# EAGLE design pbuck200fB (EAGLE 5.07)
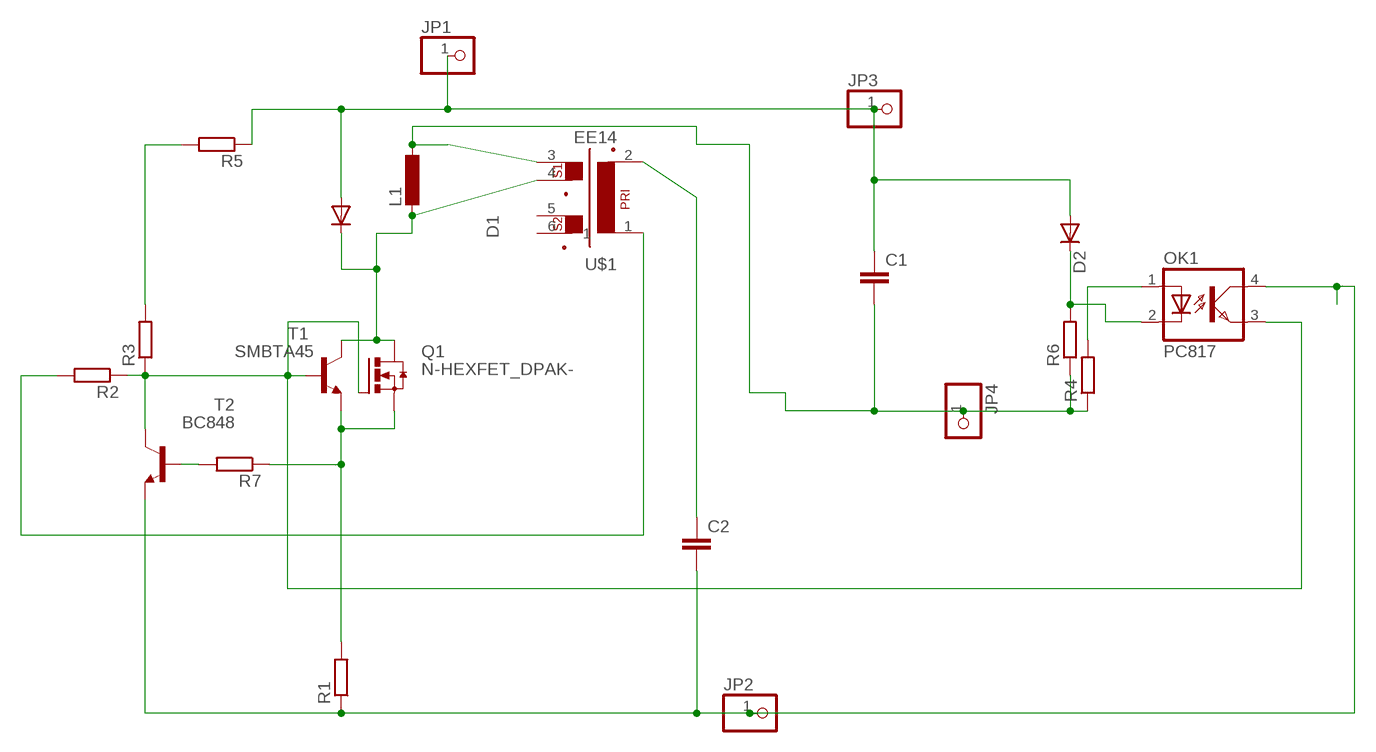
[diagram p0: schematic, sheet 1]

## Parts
C1  C-EU025-025X050  [C025-025X050]
C2  C-EUC0805  [C0805]
D1  DIODE-SMC  [SMC]
D2  DIODE-MINIMELF  [MINIMELF]
JP1  PINHD-1X11MM6  [1X1MM8]
JP2  PINHD-1X11MM6  [1X1MM8]
JP3  PINHD-1X11MM6  [1X1MM8]
JP4  PINHD-1X11MM6  [1X1MM8]
L1  L-EU0204/5  [0204/5]
OK1  PC817  [DIL04]
Q1  N-HEXFET_DPAK-  [TO252]
R1  R-EU_R1206  [R1206]
R2  R-EU_R0805  [R0805]
R3  R-EU_R1206  [R1206]
R4  R-EU_R0805  [R0805]
R5  R-EU_R1206  [R1206]
R6  R-EU_R0805  [R0805]
R7  R-EU_R1206  [R1206]
T1  SMBTA45  BC848  [SOT23]
T2  BC848  [SOT23]
U$1  EE14  [EE14]

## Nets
-: C1.1 D1.A D2.A JP1.1 JP3.1 R5.1
B1C2: OK1.3(EMIT) Q1.1(G) R2.1 R3.1 T1.B T2.C
C1: D1.C L1.2 Q1.3(D) T1.C U$1.4
EB: Q1.2(S) R1.2 R7.1 T1.E
N$1: R3.2 R5.2
N$3: R7.2 T2.B
N$4: R2.2 U$1.1
N$6: C2.1 U$1.2
N$7: D2.C OK1.2(C) R6.2
N$8: OK1.1(A) R4.2
OUT+: C1.2 JP4.1 L1.1 R4.1 R6.1 U$1.3
VPLUS: C2.2 JP2.1 OK1.4(COL) R1.1 T2.E
Unconnected: U$1.5 U$1.6

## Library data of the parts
C1 C2 = rcl:C-EU: CAPACITOR, European symbol
D1 D2 = diode:DIODE-: DIODE
JP1-JP4 = pinhead:PINHD-1X1: PIN HEADER
L1 = rcl:L-EU: INDUCTOR, European symbol
OK1 = optocoupler:PC817: SHARP OPTO COUPLER
Q1 = transistor-power:N-HEXFET_?-*: HEXFET® Power MOSFET
R1-R7 = rcl:R-EU_: RESISTOR, European symbol
T1 T2 = transistor:BC848: NPN TRANSISTOR
U$1 = trafo:EE14

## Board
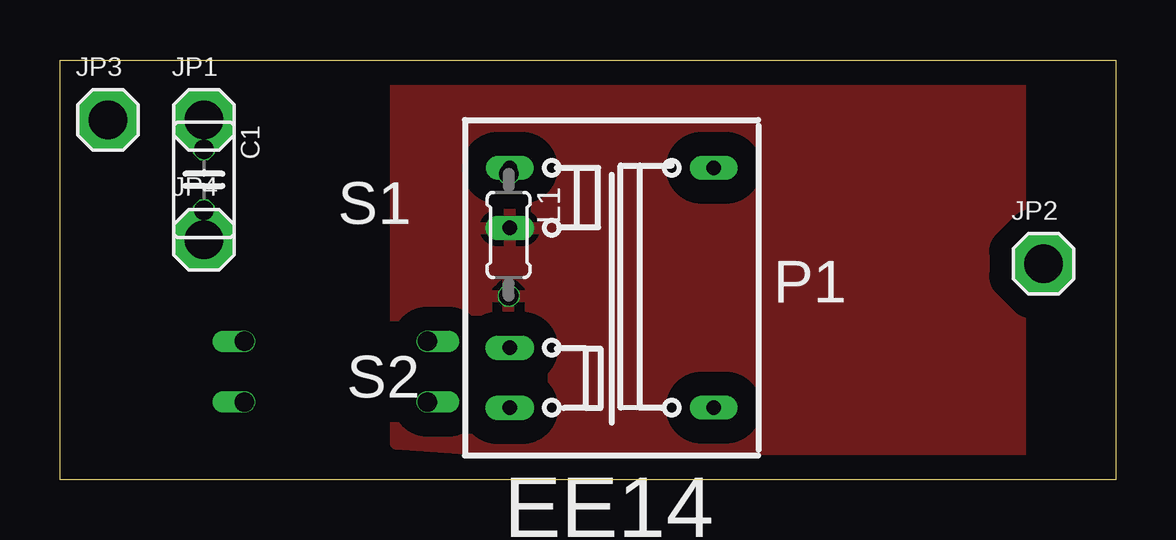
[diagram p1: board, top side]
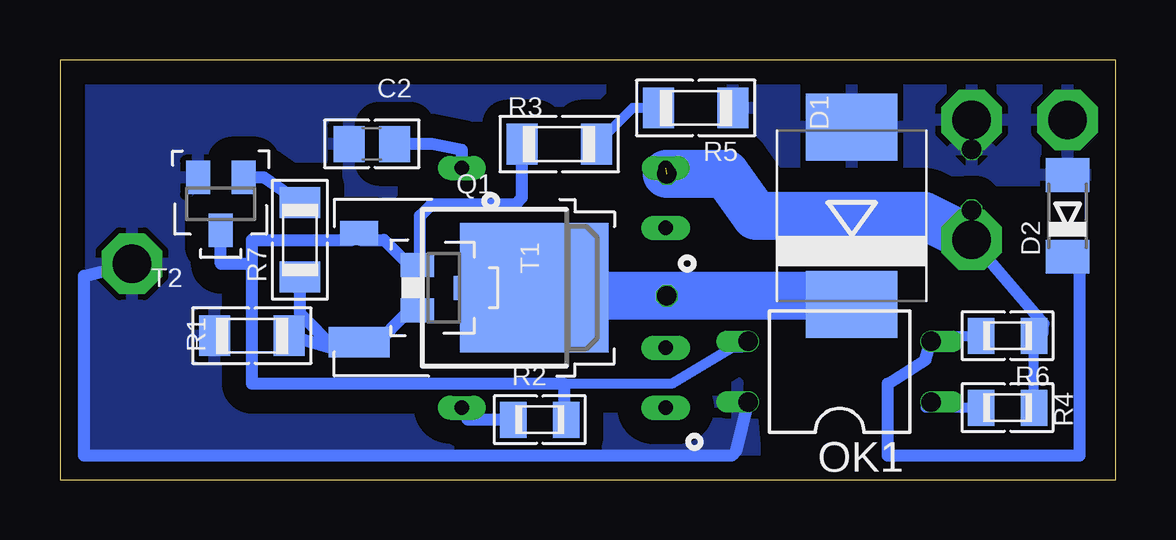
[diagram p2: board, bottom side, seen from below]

Size 44 x 17.5 mm. Coordinates in mm from the lower left corner, seen from the top.
Outline: 0,17.5 44,17.5 44,0 0,0 0,17.5
Copper layers (1*16): Top 0.035mm / dielectric 1.5mm / Bottom 0.035mm
Design rules "default": minimum track width 10mil, minimum drill 20mil, track to track 8mil, track to pad 8mil, pad to pad 8mil, via to via 8mil, smd to smd 8mil, copper to edge 40mil, drill to drill 8mil, minimum pad ring 1mil, minimum via ring 8mil, stop-mask expansion 4mil, vias tented up to drill 0mil, thermal gap 10mil

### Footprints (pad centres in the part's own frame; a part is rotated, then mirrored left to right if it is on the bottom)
C025-025X050 = drill 0.813 octagon: 1 -1.27,0; 2 1.27,0
C0805 = smd 1.3 x 1.5: 1 -0.95,0; 2 0.95,0
SMC = smd 2.8 x 3.8: A 3.7,0; C -3.7,0
MINIMELF = smd 1.4 x 1.8: A 1.7,0; C -1.7,0
1X1MM8 = drill 1.6 pad 2.54 octagon: 1 0,0
0204/5 = drill 0.813 octagon: 1 -2.54,0; 2 2.54,0
DIL04 = drill 0.813 offset: 1 -1.27,-3.81; 2 1.27,-3.81; 3 1.27,3.81; 4 -1.27,3.81
TO252 = smd 1 x 1.6: 1 -2.28,-3.53 | smd 1.27 x 2.54: 2 2.28,-3.53 | smd 5.4 x 6.2: 3 0,3.77
R1206 = smd 1.3 x 1.7: 1 -1.55,0; 2 1.55,0
R0805 = smd 1.1 x 1.5: 1 -1.1,0; 2 1.1,0
SOT23 = smd 1 x 1.4: B -0.95,-1.1; C 0,1.1; E 0.95,-1.1
EE14 = drill 0.6 pad 1 long: 1 4.25,-5; 2 4.25,5; 3 -4.25,5 | drill 0.6 pad 1.016 long: 4 -4.25,2.5; 5 -4.25,-2.5; 6 -4.25,-5

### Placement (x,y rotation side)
C1  6,12.5 270 top
C2  31,14 180 bottom
D1  11,11 90 bottom
D2  2,11 90 bottom
JP1  6,15 0 top
JP2  41,9 0 top
JP3  2,15 0 top
JP4  6,10 0 top
L1  18.7,10.2 270 top
OK1  11.5,4.5 90 bottom
Q1  28,8 270 bottom
R1  36,6 0 bottom
R2  24,2.5 180 bottom
R3  23.19,13.99 0 bottom
R4  4.5,3 180 bottom
R5  17.5,15.5 180 bottom
R6  4.5,6 180 bottom
R7  34,10 90 bottom
T1  28,8 270 bottom
T2  37.3,11.5 180 bottom
U$1  23,8 0 top

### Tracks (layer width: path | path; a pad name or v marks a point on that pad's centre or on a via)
-
  pour Bottom (isolate 1, rank 2): 1.5,16.5 16,16.5 16,13.5 15,12.5 1,12.5
B1C2
  Bottom 0.406: 23,4 18.5,4 16,5.5 15.58,5.5 OK1.3 | 31.8,10 31.2,10 31.17,10.03
  Bottom 0.5: R3.1 24.74,11.76 25,11.5 28.5,11.5 29,11 29,9.05 T1.B 29.45,8.95 30.5,10 31.5,10 Q1.1 31.17,10.03 | T2.C 37.3,9 36,9 | 36,9 36,10 31.8,10 | R2.1 23,2.6 23,4 36,4 36,9
C1
  Bottom 0.406: 24.14,7.66 Q1.3 26.65,7.75 T1.C
  Bottom 0.5: L1.2 18.56,7.8 | D1.C 11.14,7.66
  Bottom 2: 11.14,7.66 L1.2 24.14,7.66
  pour Top (isolate 1, rank 2): 14,16.5 40,16.5 40,1 21,1 14,1.5
EB
  Bottom 0.406: 31.5,5.4 30.74,5.4 30.67,5.47
  Bottom 0.5: T1.E 29.45,7.05 31,5.5 31.5,5.5 Q1.2 30.67,5.47 | 31.5,5.4 32.5,5.43 | 32.5,5.43 R1.2 | R7.1 34,6.93 32.5,5.43
N$1
  Bottom 0.406: R5.2 20.13,15.5 R3.2
N$3
  Bottom 0.5: T2.B 35.5,12.6 R7.2
N$4
  Bottom 0.5: R2.2 27,2.5 U$1.1
N$6
  Bottom 0.5: U$1.2 27.25,13.75 28.5,14 C2.1
N$7
  Bottom 0.406: R6.2 7.46,6 OK1.2
  Bottom 0.5: OK1.2 7.92,5 9.5,4 9.5,1 1.5,1 1.5,9 1.8,9.3 D2.C
N$8
  Bottom 0.406: R4.2 7.92,3 OK1.1
OUT+  (1 unrouted)
  Bottom 0.406: 3,6.5 3,6.1 R6.1 R4.1
  Bottom 0.5: C1.2 JP4.1 3,6.5
  Bottom 2: JP4.1 8,11 15,11 16.24,12.74 L1.1
VPLUS
  Bottom 0.5: JP2.1 43,8.5 43,1 16,1 15.81,1.19 OK1.4
  pour Bottom (isolate 1, rank 3): 20.5,17 43.5,17 44,1 15,1 15.5,6.5 21.5,6.5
